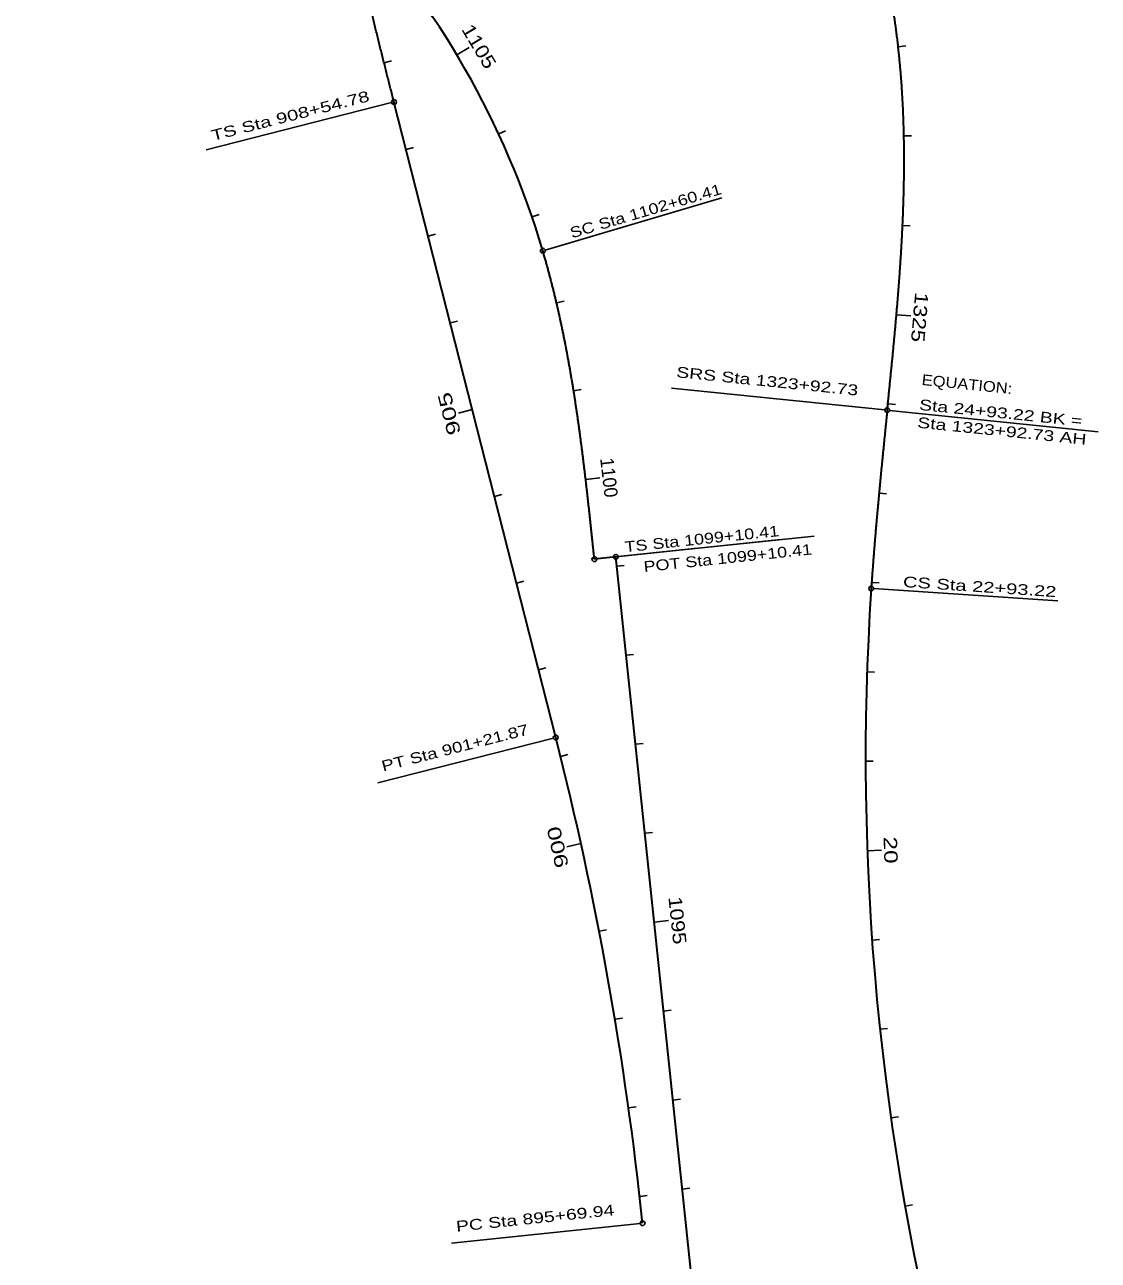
# Model space of a CAD drawing. Extents: x 771045 to 775849, y 632284 to 641017.
# Drawn here: x 771963 to 773163, y 634461 to 635842 of the extents above; entities that cross this region are included whole.
import ezdxf
from ezdxf.enums import TextEntityAlignment as Align

# ---------------------------------------------------------------- set-up
doc = ezdxf.new("R2010")
doc.units = 0
doc.header["$LTSCALE"] = 4.8
for name, color, linetype, lineweight in [('1', 7, 'Continuous', 35), ('30', 7, 'Continuous', 25), ('33', 7, 'Continuous', 25)]:
    doc.layers.add(name, color=color, linetype=linetype, lineweight=lineweight)

msp = doc.modelspace()

# ---------------------------------------------------------------- linework, layer by layer
at = {"layer": '1'}
msp.add_line((772556.742, 635045.345), (772375.975, 635755.616), dxfattribs=at)
msp.add_lwpolyline([(772765.333, 633900.748), (772623.816, 635247.194), (772599.947, 635244.686)], dxfattribs=at)
for centre, radius, start, end in [((771626.667, 635318.157), 954.93, 16.5, 69.36), ((775767.819, 635022.104), 2864.789, 176.20056, 194.60278), ((768855.027, 634103.242), 3819.719, 6, 14.27889)]:
    msp.add_arc(centre, radius, start, end, dxfattribs=at)
for points in [[(772375.975, 635755.616), (772374.309, 635762.164), (772372.643, 635768.713), (772370.979, 635775.261), (772369.318, 635781.811), (772367.66, 635788.361), (772366.006, 635794.912), (772364.357, 635801.465), (772362.714, 635808.018), (772361.078, 635814.574), (772359.449, 635821.132), (772357.829, 635827.691), (772356.218, 635834.253), (772354.616, 635840.817), (772353.026, 635847.384), (772351.448, 635853.954), (772349.882, 635860.527), (772348.329, 635867.103), (772346.791, 635873.682), (772345.267, 635880.265), (772343.76, 635886.851), (772342.27, 635893.442), (772340.797, 635900.036), (772339.343, 635906.634), (772337.908, 635913.237), (772336.493, 635919.844), (772335.099, 635926.455), (772333.727, 635933.071), (772332.378, 635939.692), (772331.053, 635946.318), (772329.752, 635952.948), (772328.477, 635959.583), (772327.227, 635966.223), (772326.005, 635972.869), (772324.811, 635979.519), (772323.646, 635986.175), (772322.51, 635992.835), (772321.405, 635999.501), (772320.332, 636006.172), (772319.29, 636012.848), (772318.282, 636019.529), (772317.308, 636026.215), (772316.369, 636032.907), (772315.466, 636039.603), (772314.6, 636046.304), (772313.771, 636053.009), (772312.98, 636059.72), (772312.229, 636066.435), (772311.519, 636073.154), (772310.849, 636079.877), (772310.222, 636086.605), (772309.637, 636093.336), (772309.096, 636100.071), (772308.6, 636106.81), (772308.149, 636113.552), (772307.745, 636120.296), (772307.388, 636127.044), (772307.079, 636133.793), (772306.819, 636140.545), (772306.609, 636147.298), (772306.45, 636154.053), (772306.343, 636160.809), (772306.288, 636167.566), (772306.287, 636174.322), (772306.34, 636181.079), (772306.448, 636187.835), (772306.612, 636194.59), (772306.832, 636201.343), (772307.111, 636208.094), (772307.448, 636214.842), (772307.844, 636221.587), (772308.301, 636228.328), (772308.818, 636235.065), (772309.398, 636241.797), (772310.04, 636248.523)], [(772927.218, 635411.124), (772927.867, 635417.51), (772928.514, 635423.897), (772929.161, 635430.283), (772929.805, 635436.669), (772930.447, 635443.056), (772931.085, 635449.443), (772931.72, 635455.831), (772932.349, 635462.219), (772932.973, 635468.607), (772933.591, 635474.996), (772934.203, 635481.386), (772934.807, 635487.777), (772935.402, 635494.168), (772935.989, 635500.56), (772936.566, 635506.953), (772937.134, 635513.346), (772937.69, 635519.741), (772938.235, 635526.137), (772938.768, 635532.534), (772939.287, 635538.932), (772939.794, 635545.331), (772940.286, 635551.73), (772940.763, 635558.132), (772941.224, 635564.534), (772941.669, 635570.938), (772942.098, 635577.342), (772942.508, 635583.748), (772942.9, 635590.155), (772943.274, 635596.563), (772943.627, 635602.972), (772943.96, 635609.382), (772944.272, 635615.794), (772944.563, 635622.206), (772944.831, 635628.619), (772945.075, 635635.034), (772945.296, 635641.449), (772945.493, 635647.865), (772945.664, 635654.281), (772945.81, 635660.698), (772945.929, 635667.116), (772946.021, 635673.534), (772946.084, 635679.953), (772946.12, 635686.372), (772946.126, 635692.791), (772946.102, 635699.21), (772946.048, 635705.628), (772945.962, 635712.047), (772945.844, 635718.465), (772945.694, 635724.882), (772945.51, 635731.298), (772945.292, 635737.713), (772945.04, 635744.127), (772944.752, 635750.54), (772944.429, 635756.95), (772944.068, 635763.359), (772943.671, 635769.766), (772943.235, 635776.17), (772942.761, 635782.571), (772942.247, 635788.97), (772941.693, 635795.365), (772941.099, 635801.756), (772940.463, 635808.143), (772939.785, 635814.526), (772939.065, 635820.905), (772938.302, 635827.278), (772937.494, 635833.646), (772936.642, 635840.008), (772935.745, 635846.364), (772934.802, 635852.713), (772933.813, 635859.055), (772932.777, 635865.39), (772931.693, 635871.717), (772930.561, 635878.035), (772929.38, 635884.344)], [(772599.947, 635244.686), (772599.453, 635249.389), (772598.958, 635254.093), (772598.463, 635258.797), (772597.966, 635263.5), (772597.469, 635268.204), (772596.97, 635272.907), (772596.469, 635277.61), (772595.965, 635282.313), (772595.46, 635287.016), (772594.951, 635291.718), (772594.439, 635296.42), (772593.924, 635301.122), (772593.405, 635305.823), (772592.882, 635310.524), (772592.354, 635315.224), (772591.822, 635319.924), (772591.285, 635324.623), (772590.742, 635329.321), (772590.194, 635334.019), (772589.64, 635338.716), (772589.079, 635343.412), (772588.512, 635348.108), (772587.938, 635352.803), (772587.357, 635357.497), (772586.768, 635362.19), (772586.172, 635366.882), (772585.567, 635371.573), (772584.954, 635376.262), (772584.331, 635380.951), (772583.7, 635385.638), (772583.06, 635390.325), (772582.409, 635395.009), (772581.749, 635399.693), (772581.078, 635404.375), (772580.397, 635409.055), (772579.705, 635413.734), (772579.001, 635418.411), (772578.286, 635423.086), (772577.559, 635427.76), (772576.82, 635432.431), (772576.068, 635437.101), (772575.304, 635441.769), (772574.526, 635446.434), (772573.735, 635451.097), (772572.93, 635455.758), (772572.111, 635460.416), (772571.278, 635465.072), (772570.43, 635469.725), (772569.567, 635474.375), (772568.689, 635479.023), (772567.796, 635483.667), (772566.886, 635488.309), (772565.961, 635492.947), (772565.019, 635497.582), (772564.06, 635502.214), (772563.084, 635506.842), (772562.091, 635511.466), (772561.08, 635516.086), (772560.052, 635520.703), (772559.005, 635525.315), (772557.939, 635529.924), (772556.855, 635534.527), (772555.752, 635539.127), (772554.629, 635543.721), (772553.486, 635548.311), (772552.324, 635552.895), (772551.141, 635557.475), (772549.938, 635562.049), (772548.714, 635566.618), (772547.469, 635571.181), (772546.203, 635575.738), (772544.915, 635580.289), (772543.605, 635584.833), (772542.273, 635589.372)], [(772927.218, 635411.124), (772926.945, 635408.436), (772926.672, 635405.747), (772926.399, 635403.058), (772926.126, 635400.369), (772925.853, 635397.68), (772925.581, 635394.991), (772925.308, 635392.302), (772925.036, 635389.613), (772924.764, 635386.924), (772924.493, 635384.235), (772924.222, 635381.546), (772923.951, 635378.857), (772923.68, 635376.168), (772923.41, 635373.479), (772923.141, 635370.789), (772922.872, 635368.1), (772922.604, 635365.411), (772922.336, 635362.721), (772922.068, 635360.032), (772921.802, 635357.342), (772921.536, 635354.653), (772921.271, 635351.963), (772921.006, 635349.273), (772920.743, 635346.584), (772920.48, 635343.894), (772920.218, 635341.204), (772919.957, 635338.514), (772919.697, 635335.823), (772919.438, 635333.133), (772919.179, 635330.443), (772918.922, 635327.752), (772918.666, 635325.062), (772918.411, 635322.371), (772918.157, 635319.681), (772917.905, 635316.99), (772917.653, 635314.299), (772917.403, 635311.608), (772917.154, 635308.916), (772916.906, 635306.225), (772916.66, 635303.534), (772916.415, 635300.842), (772916.171, 635298.15), (772915.929, 635295.458), (772915.689, 635292.767), (772915.45, 635290.074), (772915.212, 635287.382), (772914.976, 635284.69), (772914.742, 635281.997), (772914.509, 635279.305), (772914.278, 635276.612), (772914.048, 635273.919), (772913.821, 635271.226), (772913.595, 635268.532), (772913.371, 635265.839), (772913.149, 635263.145), (772912.929, 635260.452), (772912.71, 635257.758), (772912.494, 635255.064), (772912.279, 635252.37), (772912.067, 635249.675), (772911.857, 635246.981), (772911.649, 635244.286), (772911.443, 635241.591), (772911.239, 635238.896), (772911.037, 635236.201), (772910.837, 635233.506), (772910.64, 635230.81), (772910.445, 635228.115), (772910.253, 635225.419), (772910.063, 635222.723), (772909.875, 635220.027), (772909.689, 635217.33), (772909.507, 635214.634), (772909.326, 635211.937)]]:
    msp.add_spline(points, degree=3, dxfattribs=at)
at = {"layer": '30'}
for p, q in [((772446.268, 635808.204), (772460, 635816.414)), ((772939.468, 635817.387), (772947.914, 635818.338)), ((772364.863, 635799.45), (772373.107, 635801.523)), ((772493.002, 635719.848), (772500.713, 635723.423)), ((772945.861, 635717.627), (772954.36, 635717.798)), ((772389.486, 635702.529), (772397.723, 635704.625)), ((772530.244, 635627.09), (772538.287, 635629.84)), ((772944.359, 635617.656), (772952.85, 635617.266)), ((772414.15, 635605.618), (772422.387, 635607.715)), ((772557.693, 635530.975), (772565.969, 635532.914)), ((772438.814, 635508.708), (772447.052, 635510.804)), ((772937.531, 635517.897), (772953.471, 635516.515)), ((772576.756, 635432.831), (772585.15, 635434.172)), ((772463.478, 635411.797), (772447.973, 635407.851)), ((772927.953, 635418.357), (772936.409, 635417.499)), ((772590.226, 635333.749), (772606.117, 635335.613)), ((772488.143, 635314.886), (772496.38, 635316.983)), ((772918.033, 635318.357), (772926.496, 635317.562)), ((772624.904, 635236.845), (772633.357, 635237.733)), ((772512.807, 635217.976), (772521.044, 635220.072)), ((772909.783, 635218.701), (772918.263, 635218.118)), ((772635.356, 635137.392), (772643.81, 635138.281)), ((772537.471, 635121.065), (772545.708, 635123.162)), ((772904.663, 635118.837), (772913.159, 635118.55)), ((772645.809, 635037.94), (772654.263, 635038.829)), ((772562.075, 635024.139), (772570.324, 635026.188)), ((772903.032, 635018.855), (772911.532, 635018.865)), ((772656.262, 634938.488), (772664.716, 634939.377)), ((772584.91, 634926.784), (772569.287, 634923.335)), ((772904.89, 634918.878), (772920.88, 634919.454)), ((772605.19, 634828.865), (772613.535, 634830.48)), ((772666.715, 634839.036), (772682.627, 634840.708)), ((772910.237, 634819.026), (772918.715, 634819.628)), ((772622.9, 634730.449), (772631.284, 634731.844)), ((772677.168, 634739.584), (772685.621, 634740.472)), ((772919.065, 634719.421), (772927.517, 634720.319)), ((772687.621, 634640.132), (772696.074, 634641.02)), ((772638.027, 634631.602), (772646.445, 634632.778)), ((772931.364, 634620.186), (772939.78, 634621.378)), ((772698.074, 634540.679), (772706.527, 634541.568)), ((772650.561, 634532.394), (772659.008, 634533.349)), ((772947.118, 634521.439), (772955.488, 634522.925))]:
    msp.add_line(p, q, dxfattribs=at)
at = {"layer": '33'}
for p, q in [((772373.358, 635754.95), (772166.145, 635702.214)), ((772544.862, 635590.138), (772742.288, 635648.619)), ((772924.532, 635411.397), (772686.074, 635435.616)), ((772929.904, 635410.852), (773163.075, 635387.169)), ((772626.501, 635247.476), (772845.374, 635270.481)), ((772602.633, 635244.968), (772808.35, 635266.59)), ((772626.501, 635247.476), (772715.107, 635256.789)), ((772912.02, 635211.758), (773117.945, 635198.083)), ((772554.126, 635044.679), (772358.015, 634994.768)), ((772651.136, 634502.229), (772440.25, 634480.064))]:
    msp.add_line(p, q, dxfattribs=at)
for centre in [(772375.975, 635755.616), (772542.273, 635589.372), (772927.218, 635411.124), (772927.218, 635411.124), (772599.947, 635244.686), (772623.816, 635247.194), (772623.816, 635247.194), (772909.326, 635211.937), (772556.742, 635045.345), (772653.821, 634502.511)]:
    msp.add_circle(centre, 2.7, dxfattribs=at)

# ---------------------------------------------------------------- texts
at = {"layer": '30'}
for s, rotation, width, p in [('1105', 300.876, 1.2, (772464.619, 635813.951)), ('1325', 265.048, 1.25, (772956.105, 635515.635)), ('905', 104.279, 1.45, (772444.885, 635409.035)), ('900', 102.451, 1.4, (772566.293, 634924.369)), ('20', 272.065, 1.35, (772923.588, 634919.281)), ('1095', 276, 1.2, (772685.395, 634840.207))]:
    msp.add_text(s, height=15, rotation=rotation, dxfattribs=dict(at, width=width)).set_placement(p, align=Align.CENTER)
msp.add_text('1100', height=15, rotation=276.688, dxfattribs=at).set_placement((772608.901, 635335.054), align=Align.CENTER)
at = {"layer": '33'}
for s, rotation, width, p in [('TS Sta 908+54.78', 14.279, 1.4, (772173.42, 635711.995)), ('SC Sta 1102+60.41', 16.5, 1.25, (772574.696, 635603.147)), ('SRS Sta 1323+92.73', 354.201, 1.35, (772691.041, 635448.035)), ('EQUATION:', 354.201, 1.15, (772965.272, 635439.424)), ('Sta 24+93.22 BK = ', 354.201, 1.35, (772962.443, 635411.567)), ('Sta 1323+92.73 AH', 354.201, 1.35, (772960.422, 635391.67)), ('TS Sta 1099+10.41', 6, 1.25, (772634.338, 635252.322)), ('POT Sta 1099+10.41', 6, 1.25, (772655.625, 635230.223)), ('CS Sta 22+93.22', 356.201, 1.4, (772944.514, 635213.609)), ('PT Sta 901+21.87', 14.279, 1.3, (772363.842, 635007.264)), ('PC Sta 895+69.94', 6, 1.35, (772445.977, 634492.952))]:
    msp.add_text(s, height=12, rotation=rotation, dxfattribs=dict(at, width=width)).set_placement(p)

doc.saveas('drawing.dxf')
